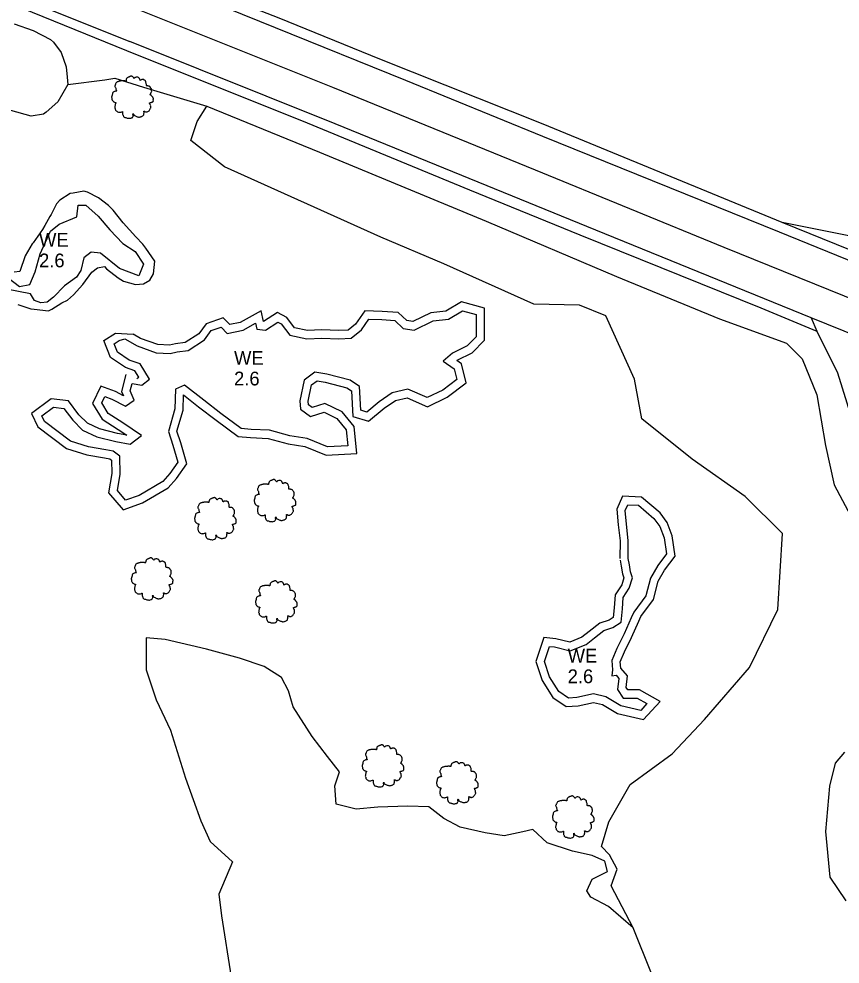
# Model space of a CAD drawing. Extents: x 2160437 to 2172832, y 205694 to 212444.
# Drawn here: x 2164009 to 2164307.9, y 209800.2 to 210144.2 of the extents above; entities that cross this region are included whole.
import ezdxf

# ---------------------------------------------------------------- set-up
doc = ezdxf.new("R2010")
doc.units = 0
for name, color, linetype in [('RD_EX_Driveway', 7, 'Continuous'), ('RD_EX_H2O_Pond', 7, 'Continuous'), ('RD_EX_H2O_txCode', 7, 'Continuous'), ('RD_EX_LaneStripe', 7, 'Continuous'), ('RD_EX_Road', 7, 'Continuous'), ('RD_EX_VEG', 7, 'Continuous'), ('RD_EX_VEG_ShrubLine', 7, 'Continuous'), ('RD_EX_VEG_TreeLine', 7, 'Continuous')]:
    doc.layers.add(name, color=color, linetype=linetype)

# ---------------------------------------------------------------- blocks, each defined once
blk = doc.blocks.new('T2')
at = {"layer": 'RD_EX_VEG'}
for points in [[(0.05, 7.21), (-0.25, 7.24), (-0.57, 7.14), (-0.82, 7.04), (-1.05, 6.96), (-1.27, 6.86), (-1.57, 6.69), (-1.8, 6.49), (-1.92, 6.24), (-1.97, 6.01), (-2.02, 5.74), (-2.02, 5.56), (-2.15, 5.54), (-2.3, 5.56), (-2.55, 5.64), (-2.8, 5.64), (-3.05, 5.64), (-3.4, 5.61), (-3.75, 5.61), (-4.02, 5.56), (-4.35, 5.51), (-4.72, 5.39), (-5.07, 5.26), (-5.37, 5.01), (-5.62, 4.54), (-5.75, 4.19), (-5.9, 3.94), (-5.75, 3.49), (-5.57, 3.14), (-5.55, 2.94), (-5.47, 2.52), (-5.37, 2.29), (-5.25, 2.09), (-5.32, 2.07), (-5.7, 2.02), (-6, 1.92), (-6.42, 1.69), (-6.64, 1.47), (-6.74, 1.14), (-6.77, 0.79), (-6.87, 0.59), (-6.94, 0.32), (-6.97, 0.24), (-7.02, -0.08), (-6.92, -0.53), (-6.89, -0.88), (-6.77, -1.11), (-6.62, -1.28), (-6.44, -1.53), (-6.05, -1.76), (-5.72, -1.86), (-5.52, -1.88), (-5.7, -2.38), (-5.75, -2.73), (-5.87, -3.13), (-5.87, -3.21), (-5.92, -3.68), (-5.77, -4.01), (-5.7, -4.38), (-5.52, -4.61), (-5.25, -4.91), (-4.92, -5.13), (-4.42, -5.26), (-4.02, -5.23), (-3.45, -5.06), (-3.2, -4.98), (-3.22, -5.16), (-3.2, -5.53), (-3.2, -5.96), (-3.05, -6.28), (-2.95, -6.56), (-2.8, -6.81), (-2.47, -7.03), (-2.07, -7.11), (-1.65, -7.26), (-1.2, -7.33), (-0.7, -7.36), (-0.1, -7.21), (0.18, -7.08), (0.28, -6.91), (0.48, -6.53), (0.43, -6.31), (0.45, -5.71), (0.55, -5.88), (0.73, -6.23), (1.23, -6.53), (1.63, -6.71), (2.1, -6.86), (2.4, -6.93), (2.88, -6.86), (3.25, -6.78), (3.63, -6.66), (3.93, -6.38), (4.1, -6.11), (4.15, -5.83), (4.23, -5.46), (4.28, -5.28)], [(4.28, -5.28), (4.2, -5.11), (4.15, -4.86), (4.23, -4.88), (4.4, -4.93), (4.68, -5.06), (4.9, -5.13), (5.23, -5.11), (5.5, -5.01), (5.95, -4.73), (6.22, -4.26), (6.5, -3.86), (6.57, -3.53), (6.52, -3.31), (6.5, -2.81), (6.3, -2.56), (6.25, -2.43), (6.15, -2.03), (6.22, -1.98), (6.5, -1.93), (6.87, -1.81), (7.15, -1.68), (7.37, -1.51), (7.45, -1.28), (7.42, -0.88), (7.47, -0.48), (7.4, -0.33), (7.3, -0.18), (7.22, 0.02), (7.07, 0.17), (6.97, 0.32), (6.87, 0.42), (6.75, 0.57), (6.57, 0.69), (6.42, 0.74), (6.37, 0.89), (6.52, 1.09), (6.57, 1.19), (6.6, 1.42), (6.82, 1.77), (6.87, 2.17), (6.82, 2.59), (6.77, 2.87), (6.62, 3.14), (6.42, 3.39), (6.3, 3.56), (6.12, 3.69), (5.8, 3.81), (5.55, 3.86), (5.2, 3.86), (5, 3.91), (5.03, 3.96), (5.03, 4.11), (5.03, 4.39), (4.95, 4.84), (4.8, 5.34), (4.8, 5.36), (4.7, 5.61), (4.48, 5.81), (4.3, 5.91), (4.1, 6.04), (3.85, 6.06), (3.55, 6.06), (3.28, 6.01), (3.08, 5.91), (2.9, 5.79), (2.83, 5.94), (2.73, 6.24), (2.68, 6.39), (2.53, 6.56), (2.3, 6.76), (1.85, 6.89), (1.23, 6.81), (0.93, 6.61), (0.78, 6.44), (0.73, 6.56), (0.53, 6.76), (0.43, 6.94), (0.25, 7.06), (0.1, 7.16), (0, 7.21)]]:
    blk.add_spline(points, degree=3, dxfattribs=at)

msp = doc.modelspace()

# ---------------------------------------------------------------- linework, layer by layer
at = {"layer": 'RD_EX_Driveway'}
msp.add_lwpolyline([(2164297.36, 210035.43), (2164299.48, 210030.49), (2164306.96, 210015.4), (2164313.81, 209993.51), (2164315.79, 209986.93), (2164328.32, 209985.83), (2164338.5, 209987.53), (2164336.08, 209999.47), (2164336.49, 210003.07), (2164341.75, 210009.48), (2164346.67, 210011.3), (2164351.12, 210013.61)], dxfattribs=at)
at = {"layer": 'RD_EX_H2O_Pond'}
msp.add_lwpolyline([(2164005.05, 210049.91), (2164009.21, 210046.73), (2164013.01, 210047.44), (2164014.93, 210052.16), (2164016.75, 210058.66), (2164020.44, 210066.92), (2164023.68, 210069.49), (2164030.09, 210072.15), (2164030.52, 210076.34), (2164033.36, 210076.39), (2164037.8, 210072.37), (2164042.07, 210067.41), (2164046.8, 210062.42), (2164051.34, 210059.55), (2164054.39, 210054.95), (2164052.61, 210050.71), (2164045.63, 210053.34), (2164038.69, 210058.9), (2164035.32, 210059.26), (2164032.59, 210057.18), (2164031.54, 210052.55), (2164029.95, 210050.2), (2164025.61, 210047.04), (2164021.6, 210042.89), (2164019.27, 210041.04), (2164016.98, 210040.87), (2164014.66, 210041.72), (2164013.18, 210044.06), (2164004.47, 210045.79)], dxfattribs=at)
for points in [[(2164047.54, 210027.77), (2164052.02, 210025.18), (2164058.93, 210022.64), (2164064.09, 210022.37), (2164066.59, 210023), (2164070.61, 210023.54), (2164076.5, 210027.33), (2164079.02, 210030.71), (2164082.57, 210031.94), (2164084.76, 210029.71), (2164090.62, 210030.88), (2164095.09, 210033.38), (2164095.58, 210031.24), (2164098.8, 210030.94), (2164103.21, 210033.83), (2164104.47, 210033.15), (2164107.57, 210029.07), (2164113.73, 210027.7), (2164119.19, 210027.97), (2164125.4, 210027.77), (2164129.91, 210027.92), (2164133.69, 210031.03), (2164136.37, 210034.88), (2164141.04, 210034.72), (2164145.78, 210034.34), (2164148.85, 210031.53), (2164152.88, 210030.88), (2164159.79, 210034.27), (2164165.38, 210034.83), (2164170.49, 210037.95), (2164175.41, 210036.6), (2164175.44, 210028.49), (2164172.21, 210025.13), (2164166.83, 210022.49), (2164163.38, 210019.59), (2164167.42, 210016.83), (2164168.43, 210012.9), (2164163.28, 210009.02), (2164157.64, 210006.32), (2164150.54, 210009.36), (2164144.88, 210008.11), (2164140.12, 210004.83), (2164135.58, 210001.1), (2164133.39, 210001.72), (2164132.96, 210010.43), (2164129.6, 210012.71), (2164121.09, 210014.88), (2164116.74, 210015.62), (2164112.8, 210012.7), (2164111.24, 210005.18), (2164111.5, 210002.13), (2164115.15, 209999.42), (2164120.06, 210001.01), (2164124.75, 209998.74), (2164128.14, 209994.64), (2164128.66, 209988.83), (2164121.35, 209988.43), (2164113.91, 209991.51), (2164107.59, 209992.41), (2164100.24, 209994.49), (2164093.53, 209994.78), (2164089.91, 209995.14), (2164082.54, 210000.53), (2164076.24, 210005.38), (2164069.23, 210010.9), (2164066.04, 210009.39), (2164065.74, 210002.26), (2164063.38, 209994.02), (2164065.04, 209989.02), (2164066.79, 209982.84), (2164063.93, 209978.72), (2164061.38, 209975.83), (2164052.71, 209970.77), (2164047.83, 209968.98), (2164044.81, 209972.55), (2164045.79, 209978.53), (2164045.7, 209985.05), (2164043.34, 209986.88), (2164040.67, 209987.35), (2164034.37, 209988.42), (2164027.73, 209990.49), (2164018.32, 209997.62), (2164017.37, 209999.67), (2164021.6, 210002.82), (2164025.34, 210002.35), (2164028.55, 209998.1), (2164032.16, 209994.51), (2164037.32, 209992.08), (2164044.27, 209990.31), (2164049.43, 209989.38), (2164053.63, 209992.61), (2164046.81, 209997.21), (2164041.48, 210000.61), (2164039.16, 210004.4), (2164040.28, 210006.78), (2164042.85, 210005.82), (2164047.84, 210003.17), (2164050.93, 210005.39), (2164049.51, 210008.78), (2164050.15, 210011.44), (2164053.76, 210010.91), (2164056.56, 210013.02), (2164053.17, 210018.61), (2164049.09, 210019.95), (2164044.84, 210022.92), (2164043.65, 210025.91), (2164045.49, 210027.07)], [(2164230.73, 209947.74), (2164230.79, 209954.37), (2164230.11, 209960.31), (2164229.64, 209965.26), (2164230.59, 209967.38), (2164234.49, 209967.18), (2164240.16, 209962.4), (2164242.33, 209959.42), (2164243.84, 209955.33), (2164244.67, 209949.47), (2164241.54, 209945.26), (2164238.86, 209940.66), (2164237.24, 209934.22), (2164232.76, 209928.21), (2164231.88, 209926.17), (2164229.26, 209920.35), (2164226.66, 209915.06), (2164224.84, 209910.65), (2164225.1, 209907.33), (2164224.83, 209905.11), (2164226.35, 209905.3), (2164227.36, 209904.13), (2164226.85, 209900.16), (2164228.95, 209896.94), (2164234.08, 209896.94), (2164237.6, 209895.01), (2164235.31, 209892.49), (2164228.06, 209894.2), (2164222.59, 209897.47), (2164218.11, 209898.51), (2164212.1, 209897.21), (2164209.01, 209897.02), (2164205.53, 209899.36), (2164202.15, 209904.7), (2164200.27, 209910.31), (2164202.09, 209915.79), (2164203.93, 209915.6), (2164209.7, 209914.23), (2164215.44, 209916.53), (2164218.47, 209918.9), (2164221.85, 209921.56), (2164225.19, 209922.67), (2164228.19, 209924.61), (2164228.71, 209929.53), (2164228.93, 209933.54), (2164231.14, 209936.94), (2164232.32, 209940.73), (2164231.57, 209942.95), (2164231.19, 209945.52)]]:
    msp.add_lwpolyline(points, close=True, dxfattribs=at)
at = {"layer": 'RD_EX_LaneStripe'}
msp.add_lwpolyline([(2164053.38, 210147.25), (2164123.11, 210119.29), (2164196.85, 210089.22), (2164265.56, 210061.12), (2164336.65, 210032.35), (2164405.58, 210004.27), (2164479.64, 209974.11), (2164550.79, 209945.02), (2164618.79, 209917.14), (2164687.93, 209889.27), (2164713.96, 209878.5)], dxfattribs=at)
at = {"layer": 'RD_EX_Road'}
for points in [[(2163339.36, 210424.64), (2163420.98, 210391.42), (2163497.03, 210360.67), (2163575.97, 210328.25), (2163667.7, 210290.66), (2163742.47, 210260.32), (2163822.04, 210228.09), (2163909.42, 210192.51), (2163985.2, 210161.6), (2164049.4, 210135.92)], [(2163337.83, 210421.74), (2163444.25, 210378.23), (2163530.28, 210343.44), (2163596.65, 210315.89), (2163680.6, 210281.31), (2163754.64, 210251.65), (2163815.16, 210227.17), (2163865.96, 210206.52), (2163934.01, 210179.08), (2164048.1, 210132.64)], [(2164719.32, 209893.53), (2164711.43, 209896.75), (2164660.02, 209917.67), (2164574.62, 209952.59), (2164515.44, 209976.77), (2164441.71, 210006.87), (2164361.41, 210039.86), (2164286.82, 210070.11), (2164199.81, 210105.86), (2164140.4, 210129.54), (2164103.67, 210144.43), (2164088.45, 210150.38), (2164055.87, 210164.02)], [(2164054.87, 210160.36), (2164149.67, 210121.83), (2164199.63, 210101.52), (2164285.68, 210066.64), (2164373.04, 210031.13), (2164462.58, 209994.39), (2164557.26, 209955.73), (2164630.42, 209925.95), (2164717.47, 209890.02)], [(2164708.26, 209867.65), (2164638.19, 209896.35), (2164549.03, 209932.58), (2164448.32, 209973.61), (2164369.65, 210006), (2164351.12, 210013.61), (2164297.36, 210035.43), (2164218.93, 210067.29), (2164124.14, 210105.98), (2164049.4, 210135.92)], [(2164048.1, 210132.64), (2164113.85, 210106.31), (2164173.06, 210081.93), (2164213.22, 210065.52), (2164279.04, 210039.01), (2164299.48, 210030.49)]]:
    msp.add_lwpolyline(points, dxfattribs=at)
at = {"layer": 'RD_EX_VEG_ShrubLine'}
for points in [[(2164026.78, 210120.26), (2164040.24, 210121.95), (2164043.93, 210122.6), (2164054.32, 210119.33)], [(2164054.32, 210119.33), (2164077.41, 210112.39)], [(2164008.58, 210040.24), (2164013.26, 210038.63), (2164014.54, 210038.54), (2164019.69, 210037.86), (2164020.99, 210038.48), (2164024.56, 210040.85), (2164026.63, 210041.85), (2164028.85, 210043.74), (2164032.19, 210047.46), (2164032.19, 210047.46), (2164035.58, 210051.95), (2164037.56, 210053.59), (2164040.1, 210054.02), (2164040.92, 210053.17), (2164045.09, 210049.87), (2164047.1, 210048.73), (2164051.37, 210047.55), (2164054.28, 210047.75), (2164056.6, 210049.05), (2164057.92, 210051.34), (2164058.5, 210056), (2164058.5, 210056), (2164055.22, 210060.77), (2164054.04, 210062.14), (2164051.49, 210064.89), (2164046.95, 210069.92), (2164046.95, 210069.92), (2164043.29, 210074.49), (2164041.59, 210076.2), (2164037.96, 210079.08), (2164033.92, 210081.06), (2164032.66, 210081.45), (2164028.79, 210080.72), (2164027.64, 210080.57), (2164023.92, 210078.15), (2164022.65, 210076.91), (2164020.7, 210072.93), (2164020.26, 210072.22), (2164018.42, 210069.03), (2164017.55, 210067.49), (2164014.16, 210062.71), (2164013.86, 210062.3), (2164011.25, 210057.94), (2164009.32, 210052.27), (2164007.2, 210051.95)], [(2164047.88, 210014.8), (2164046.36, 210008.53), (2164047, 210007.01), (2164044.08, 210008.56), (2164038.75, 210010.56), (2164035.75, 210004.22), (2164039.29, 209998.45), (2164045.16, 209994.7), (2164048.21, 209992.65), (2164044.9, 209993.24), (2164038.34, 209994.92), (2164033.91, 209997), (2164030.81, 210000.08), (2164026.98, 210005.17), (2164020.77, 210005.95), (2164013.62, 210000.61), (2164015.91, 209995.68), (2164026.34, 209987.78), (2164033.67, 209985.5), (2164040.16, 209984.4), (2164042.09, 209984.06), (2164042.72, 209983.56), (2164042.79, 209978.75), (2164041.62, 209971.67), (2164046.9, 209965.45), (2164053.99, 209968.04), (2164063.31, 209973.49), (2164066.29, 209976.86), (2164070.06, 209982.29), (2164067.91, 209989.9), (2164066.52, 209994.09), (2164068.72, 210001.78), (2164068.95, 210007.3), (2164074.4, 210003.01), (2164080.74, 209998.13), (2164088.8, 209992.23), (2164093.32, 209991.79), (2164099.76, 209991.51), (2164106.97, 209989.47), (2164113.11, 209988.6), (2164120.83, 209985.4), (2164131.93, 209986), (2164131.04, 209995.84), (2164126.64, 210001.15), (2164120.28, 210004.23), (2164115.7, 210002.75), (2164114.38, 210003.73), (2164114.27, 210005), (2164115.51, 210010.97), (2164117.5, 210012.45), (2164120.47, 210011.95), (2164128.35, 210009.93), (2164130.04, 210008.78), (2164130.5, 209999.41), (2164136.27, 209997.79), (2164141.93, 210002.44), (2164146.1, 210005.31), (2164150.25, 210006.23), (2164157.71, 210003.02), (2164164.85, 210006.44), (2164171.84, 210011.71), (2164170.05, 210018.67), (2164168.34, 210019.84), (2164168.48, 210019.96), (2164174, 210022.67), (2164178.45, 210027.28), (2164178.4, 210038.89), (2164170.04, 210041.19), (2164164.4, 210037.75), (2164158.95, 210037.2), (2164152.41, 210033.99), (2164150.22, 210034.35), (2164147.05, 210037.25), (2164141.21, 210037.71), (2164134.84, 210037.93), (2164131.47, 210033.09), (2164128.79, 210030.89), (2164125.4, 210030.78), (2164119.16, 210030.97), (2164113.99, 210030.72), (2164109.29, 210031.76), (2164106.47, 210035.48), (2164103.06, 210037.32), (2164098.03, 210034.03), (2164098.02, 210034.03), (2164097.12, 210037.95), (2164089.56, 210033.73), (2164085.77, 210032.97), (2164083.39, 210035.4), (2164077.17, 210033.24), (2164074.42, 210029.56), (2164069.55, 210026.43), (2164066.02, 210025.95), (2164063.79, 210025.39), (2164059.54, 210025.61), (2164053.3, 210027.9), (2164050.62, 210029.46)], [(2164051.95, 210013.3), (2164052.59, 210013.78), (2164051.18, 210016.1), (2164047.73, 210017.24), (2164042.38, 210020.98), (2164039.95, 210027.12), (2164044.19, 210029.79), (2164050.62, 210029.46)], [(2164227.8, 209947.13), (2164228.23, 209945), (2164228.64, 209942.25), (2164229.17, 209940.7), (2164228.4, 209938.23), (2164225.98, 209934.51), (2164225.71, 209929.78), (2164225.35, 209926.35), (2164223.88, 209925.4), (2164220.4, 209924.24), (2164216.62, 209921.26), (2164213.93, 209919.16), (2164209.47, 209917.37), (2164204.43, 209918.57), (2164200, 209919.02), (2164197.11, 209910.3), (2164199.42, 209903.4), (2164203.33, 209897.22), (2164208.18, 209893.97), (2164212.51, 209894.23), (2164218.09, 209895.44), (2164221.45, 209894.66), (2164226.92, 209891.38), (2164236.34, 209889.17), (2164242.38, 209895.81), (2164234.85, 209899.94), (2164230.58, 209899.94), (2164229.97, 209900.88), (2164230.51, 209905.08), (2164228.06, 209907.91), (2164227.89, 209910.17), (2164229.39, 209913.83), (2164231.97, 209919.07), (2164234.63, 209924.96), (2164235.38, 209926.7), (2164240, 209932.9), (2164241.66, 209939.52), (2164244.04, 209943.6), (2164247.82, 209948.66), (2164246.76, 209956.06), (2164245, 209960.85), (2164242.36, 209964.46), (2164235.65, 209970.12), (2164228.69, 209970.49), (2164226.58, 209965.76), (2164227.12, 209960), (2164227.79, 209954.21), (2164227.73, 209947.76)], [(2164232.63, 209813.33), (2164223.63, 209821.17), (2164217.15, 209824.54), (2164215.7, 209826.81), (2164217.69, 209831.14), (2164223.19, 209833.91), (2164222.24, 209837.64), (2164217.61, 209839.76), (2164210.55, 209841.29), (2164201.24, 209844.36), (2164196.03, 209849.21), (2164192.46, 209848.34), (2164185.66, 209846.82), (2164178.74, 209847.98), (2164169.63, 209850.01), (2164163.62, 209853.23), (2164158.22, 209857.38), (2164150.55, 209857.68), (2164139.63, 209857.27), (2164131.79, 209856.63), (2164124.5, 209858.44), (2164123.94, 209865.11), (2164125.65, 209870.17), (2164121.26, 209875.78), (2164115.67, 209883.02), (2164108.84, 209893.8), (2164107.16, 209899.59), (2164104.59, 209904.45), (2164098.31, 209908.52), (2164089.25, 209911.48), (2164077.23, 209914.8), (2164062.17, 209918.28), (2164055.31, 209918.98), (2164055.28, 209907.33), (2164058.9, 209896.35), (2164064.12, 209885.33), (2164069.58, 209867.84), (2164075.17, 209852.27), (2164078.54, 209844.76), (2164086.74, 209837.45), (2164081.81, 209825.61), (2164082.7, 209817.77), (2164086.26, 209795.49)]]:
    msp.add_lwpolyline(points, dxfattribs=at)
at = {"layer": 'RD_EX_VEG_TreeLine'}
for points in [[(2164312.34, 210064.99), (2164286.82, 210070.11), (2164199.81, 210105.86), (2164140.4, 210129.54), (2164103.67, 210144.43)], [(2164007.31, 210142.4), (2164014.12, 210139.94), (2164020.47, 210136.64), (2164021.62, 210135.66), (2164024.31, 210131.94), (2164026.19, 210126.76), (2164026.5, 210123), (2164026.78, 210120.26), (2164023.19, 210113.96), (2164018.91, 210110.17), (2164017.97, 210109.49), (2164013.48, 210108.79), (2164006.02, 210110.84)], [(2164239.27, 209796.75), (2164232.63, 209813.33), (2164224.53, 209828.64), (2164226.71, 209834.75), (2164223.93, 209839.95), (2164221.05, 209843.03), (2164223.67, 209852), (2164231.43, 209865.51), (2164246.73, 209876.68), (2164258.51, 209889.24), (2164274.87, 209908.16), (2164285.22, 209929.21), (2164286.89, 209956.9), (2164273.38, 209970.3), (2164254.09, 209983.95), (2164235.72, 209998.56), (2164233.07, 210013.06), (2164222.61, 210036.14), (2164213.05, 210039.99), (2164196.38, 210040.4), (2164163.66, 210055), (2164140.72, 210064.75), (2164083.78, 210090.27), (2164071.59, 210099.91), (2164073.88, 210106.8), (2164077.41, 210112.39)], [(2164077.41, 210112.39), (2164118.41, 210095.66), (2164179.01, 210070.55), (2164226.49, 210050.45), (2164264.03, 210034.97), (2164288.37, 210026.21), (2164294.12, 210020.4), (2164299.38, 210007.32), (2164302.62, 209988.9), (2164305.76, 209974.54), (2164319.79, 209948.19)], [(2164309.53, 209877.34), (2164306.13, 209873.34), (2164304, 209864.94), (2164302.64, 209848.45), (2164304.16, 209831.81), (2164309.96, 209823.17)]]:
    msp.add_lwpolyline(points, dxfattribs=at)

# ---------------------------------------------------------------- block references
at = {"layer": 'RD_EX_VEG', "xscale": 1.0499999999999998, "yscale": 1.0499999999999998}
for p in [(2164050.09, 210115.7), (2164101.99, 209968.92), (2164080.28, 209962.35), (2164057.24, 209940.41), (2164102.46, 209932.06), (2164141.29, 209872.39), (2164168.36, 209866.25), (2164210.55, 209853.79)]:
    msp.add_blockref('T2', p, dxfattribs=at)

# ---------------------------------------------------------------- texts
at = {"layer": 'RD_EX_H2O_txCode'}
for s, p in [('WE', (2164016.31, 210061.25)), ('2.6', (2164016.31, 210053.75)), ('WE', (2164087.3, 210018.28)), ('2.6', (2164087.3, 210010.78)), ('WE', (2164208.74, 209909.92)), ('2.6', (2164208.74, 209902.42))]:
    msp.add_text(s, height=5, dxfattribs=at).set_placement(p)

doc.saveas('drawing.dxf')
